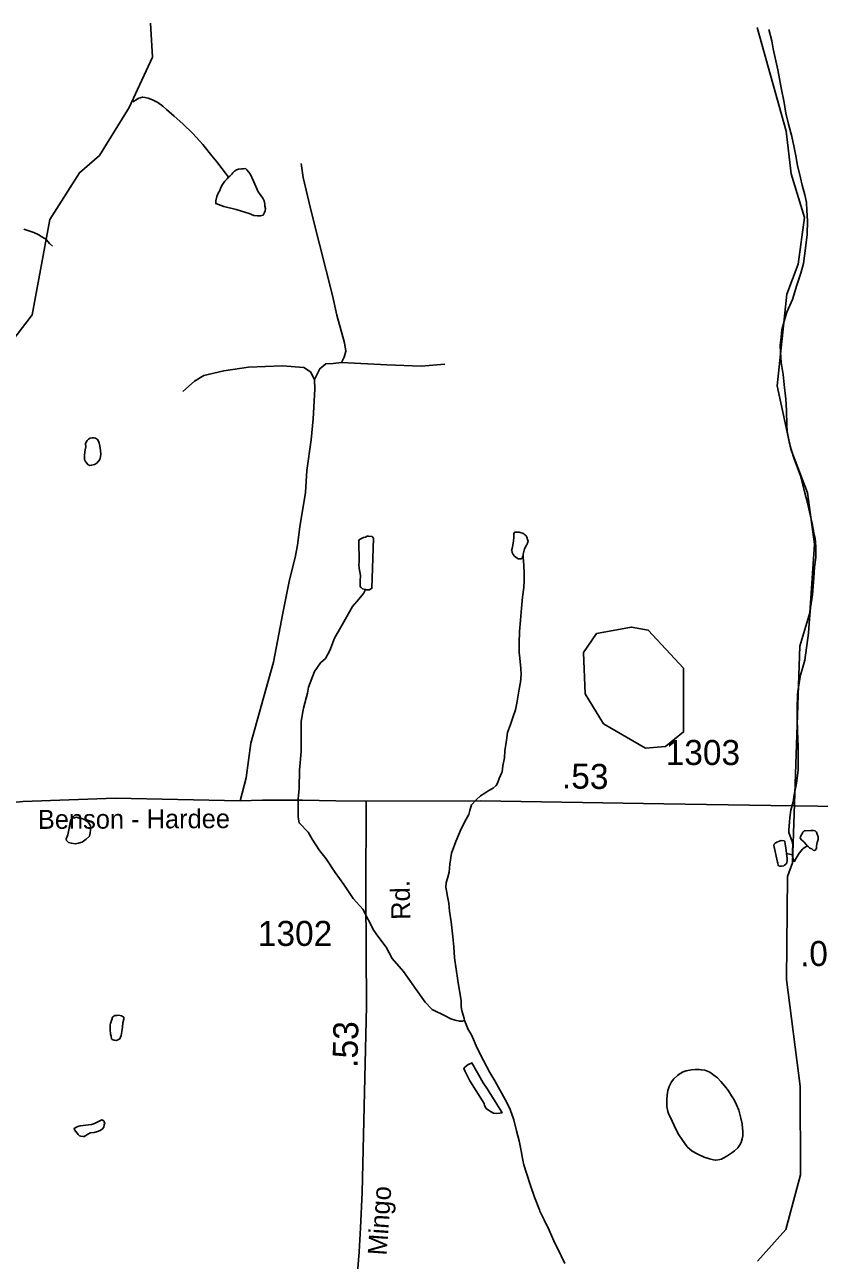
# Model space of a CAD drawing. Extents: x 2082433 to 2279600, y 546599 to 755198.
# Drawn here: x 2127316 to 2131289, y 597000 to 603173 of the extents above; entities that cross this region are included whole.
import ezdxf

# ---------------------------------------------------------------- set-up
doc = ezdxf.new("R2010")
doc.units = 0
for name, color, linetype in [('Exist Hydrographic Creek Single Shore', 7, 'Continuous'), ('Exist Hydrographic Misc Water Feature', 7, 'Continuous'), ('Exist Hydrographic Pond Under 1500 Sq Ft', 7, 'Continuous'), ('Exist Road Non-System Type 51', 7, 'Continuous'), ('Exist Road Secondary Mileage Hundredths English Label', 7, 'Continuous'), ('Exist Road Secondary Type 51 Attributed', 7, 'Continuous'), ('Exist Road Secondary Type 51 Label', 7, 'Continuous'), ('Exist Road Secondary Type 51 Number Label', 7, 'Continuous')]:
    doc.layers.add(name, color=color, linetype=linetype)

msp = doc.modelspace()

# ---------------------------------------------------------------- linework, layer by layer
at = {"layer": 'Exist Hydrographic Creek Single Shore'}
for points in [[(2127176.1, 601492.2), (2127353.7, 601723.6), (2127442.4, 602201), (2127590.5, 602434.2), (2127690.3, 602520.7), (2127839.4, 602760.5), (2127955.5, 603010.7), (2127944.6, 603180.4)], [(2130980.4, 596995.4), (2131121.5, 597153.3), (2131195.5, 597427.3), (2131193.5, 597870.3), (2131124.6, 598403.1), (2131130.5, 598918), (2131155.6, 598986.4), (2131191.4, 600068.2), (2131241.5, 600234.5), (2131264.4, 600578.5), (2131230.6, 600835.1), (2131146.5, 601053.3), (2131078.5, 601369.6), (2131126.5, 601827.9), (2131183.5, 601977.6), (2131215.7, 602209.9), (2131148.6, 602427.8), (2131122.6, 602641.5), (2130978.6, 603159.5)], [(2129019.9, 600351.6), (2129010.1, 600331.5), (2128986.1, 600303.5), (2128954.5, 600267.4), (2128896.9, 600163.1), (2128865.1, 600109), (2128841.3, 600046.9), (2128819.6, 600006.8), (2128795.4, 599984.7), (2128764.6, 599942.8), (2128735.5, 599864), (2128730.4, 599834), (2128709.8, 599758.6), (2128698.7, 599694.4), (2128697.8, 599617.3), (2128697.8, 599541.9), (2128691, 599449.4), (2128688.4, 599357.8), (2128684.1, 599306.4), (2128683.3, 599256.7), (2128683.3, 599213.9), (2128688.4, 599185.6), (2128733.4, 599138.8), (2128753.3, 599104.8), (2128789.8, 599047), (2128823.9, 599005.2), (2128868.2, 598937.3), (2128912.4, 598877.5), (2128958.6, 598807.8), (2129006.1, 598754.8), (2129061.8, 598648.6), (2129081.6, 598620.4), (2129123.7, 598564.6), (2129154.2, 598508.7), (2129210.4, 598443), (2129272.7, 598353.4), (2129318.9, 598289.5), (2129353.1, 598253.8), (2129377.1, 598241.9), (2129399, 598231.9), (2129415, 598224), (2129447.2, 598206.2), (2129469.2, 598200.2), (2129489.5, 598194.3), (2129503.4, 598194.4), (2129515.1, 598198.4)]]:
    msp.add_lwpolyline(points, dxfattribs=at)
at = {"layer": 'Exist Hydrographic Misc Water Feature'}
msp.add_line((2131155.1, 599025.4), (2131125.2, 599033.3), dxfattribs=at)
for points in [[(2131037.2, 603149.6), (2131051.3, 603093.7), (2131057.5, 603053.7), (2131081.9, 602947.9), (2131098.5, 602858), (2131112.7, 602784), (2131120.9, 602732.1), (2131135.2, 602676.2), (2131151.4, 602614.3), (2131163.7, 602560.4), (2131171.7, 602518.4), (2131179.9, 602470.5), (2131194.3, 602408.5), (2131202.5, 602372.6), (2131216.6, 602322.7), (2131224.6, 602284.7), (2131226.9, 602244.7), (2131229.1, 602192.8), (2131227.5, 602124.8), (2131219.9, 602056.7), (2131210.3, 601980.7), (2131196.5, 601932.7), (2131176.6, 601872.7), (2131154.9, 601800.5), (2131127.2, 601736.5), (2131113.5, 601692.4), (2131101.6, 601648.3), (2131097.9, 601612.4), (2131094, 601570.3), (2131094.2, 601538.3), (2131098.5, 601486.4), (2131108.8, 601426.5), (2131112.9, 601376.5), (2131121.3, 601302.6), (2131125.4, 601246.6), (2131125.8, 601172.7), (2131127.8, 601140.6), (2131131.9, 601124.6), (2131138.1, 601088.7), (2131148.1, 601050.8), (2131164.3, 600998.8), (2131194.9, 600919), (2131215.2, 600841.1), (2131229.3, 600785.2), (2131239.6, 600739.2), (2131253.9, 600681.3), (2131261.9, 600635.4), (2131268.1, 600607.4), (2131272.4, 600565.5), (2131270.8, 600511.4), (2131264.6, 600463.4), (2131260.9, 600411.5), (2131255.4, 600325.4), (2131245.7, 600259.4), (2131240, 600205.4), (2131234.3, 600133.4), (2131216.8, 599999.4), (2131207, 599963.3), (2131195.1, 599923.3), (2131181.8, 599843.3), (2131179.7, 599821.3), (2131177.9, 599761.2), (2131178.1, 599711.3), (2131180.3, 599643.3), (2131182.6, 599565.4), (2131183, 599525.4), (2131183.2, 599483.4), (2131183.2, 599449.5), (2131175.6, 599383.4), (2131163.9, 599325.4), (2131158, 599291.4), (2131146.1, 599249.3), (2131142.4, 599213.3), (2131140.3, 599189.3), (2131136.6, 599151.3), (2131136.6, 599137.3), (2131152.8, 599093.4), (2131156.9, 599075.4), (2131154.9, 599047.5), (2131155.1, 599033.4), (2131155.1, 599025.4)], [(2127857.7, 602787.8), (2127887.6, 602805.9), (2127905.4, 602812), (2127917.3, 602810), (2127933.7, 602806.1), (2127955.7, 602798.2), (2127981.7, 602784.3), (2128007.6, 602766.4), (2128025.6, 602750.5), (2128063.9, 602716.7), (2128106.2, 602678.9), (2128156.2, 602629.1), (2128206.5, 602575.3), (2128252.6, 602517.6), (2128277, 602487.6), (2128302.8, 602453.8), (2128321.1, 602431.9), (2128335.2, 602412)], [(2128335.2, 602412), (2128341.2, 602416), (2128351.2, 602426), (2128357, 602434.1), (2128365, 602442.1), (2128374.8, 602448.1), (2128384.9, 602452.1), (2128400.8, 602454.2), (2128410.9, 602454.2), (2128420.9, 602454.4), (2128426.9, 602448.4), (2128442.9, 602428.5), (2128461.1, 602388.5), (2128483.5, 602338.6), (2128493.3, 602324.7), (2128507.7, 602306.8), (2128513.6, 602292.8), (2128517.7, 602276.8), (2128517.7, 602266.8), (2128519.6, 602254.8), (2128517.9, 602242.8), (2128515.9, 602234.8), (2128507.9, 602222.7), (2128496, 602218.7), (2128480, 602218.6), (2128462, 602220.6), (2128438, 602230.4), (2128374, 602250.1), (2128311.9, 602265.9), (2128271.7, 602279.7), (2128271.7, 602293.7), (2128277.6, 602315.7), (2128283.4, 602331.8), (2128291.3, 602345.8), (2128297.3, 602359.8), (2128305.5, 602375.8), (2128317.2, 602391.9), (2128329.1, 602404), (2128335.2, 602412)], [(2127312.6, 602151.6), (2127362.7, 602135.8), (2127386.7, 602123.9), (2127398.6, 602116), (2127416.6, 602106), (2127424.8, 602098.1), (2127440.8, 602080.1), (2127454.9, 602066.2)], [(2127615.3, 601025.2), (2127619.4, 601049.2), (2127621.4, 601065.2), (2127621, 601079.3), (2127625.1, 601091.3), (2127629, 601095.3), (2127635.2, 601103.3), (2127643.2, 601107.3), (2127653, 601109.4), (2127663.1, 601109.4), (2127671.1, 601107.4), (2127681.1, 601101.5), (2127685.2, 601093.5), (2127689.1, 601083.5), (2127691.2, 601069.6), (2127695.5, 601045.5), (2127697.3, 601027.5), (2127695.5, 601015.6), (2127691.6, 601001.6), (2127677.6, 600983.5), (2127665.5, 600975.4), (2127651.6, 600973.4), (2127641.5, 600971.3), (2127633.5, 600975.3), (2127625.5, 600985.3), (2127619.6, 600991.3), (2127615.7, 601001.2), (2127615.3, 601013.2), (2127615.3, 601019.2), (2127615.3, 601025.2)], [(2129019.9, 600351.6), (2129006, 600355.5), (2128998, 600361.5), (2128993.9, 600365.5), (2128993.7, 600395.5), (2128995.7, 600421.5), (2128989.3, 600457.5), (2128987.3, 600477.4), (2128989.3, 600485.4), (2128986.9, 600599.4), (2128991, 600599.4), (2128992.8, 600603.4), (2129002.9, 600607.4), (2129010.9, 600611.5), (2129020.9, 600613.5), (2129028.9, 600617.5), (2129034.9, 600617.5), (2129052.9, 600615.7), (2129058.9, 600609.7), (2129060.9, 600605.7), (2129051.9, 600357.7), (2129039.8, 600349.7), (2129023.8, 600349.6), (2129019.9, 600351.6)], [(2129808.9, 600529), (2129808.9, 600521), (2129804.8, 600513), (2129803, 600509), (2129799.1, 600505), (2129789.3, 600504.9), (2129783.1, 600504.9), (2129779.2, 600508.9), (2129771, 600512.9), (2129764.9, 600518.8), (2129758.9, 600526.8), (2129753, 600536.8), (2129753, 600540.8), (2129750.9, 600544.8), (2129753, 600556.7), (2129754.8, 600564.7), (2129760.8, 600592.7), (2129762.6, 600612.8), (2129762.6, 600622.8), (2129762.4, 600630.8), (2129764.4, 600636.8), (2129768.3, 600638.8), (2129774.5, 600638.8), (2129782.5, 600638.9), (2129788.4, 600638.9), (2129798.5, 600634.9), (2129806.5, 600633), (2129814.5, 600627), (2129820.4, 600623), (2129822.7, 600619.1), (2129826.6, 600613.1), (2129830.7, 600601.1), (2129832.7, 600593.1), (2129830.7, 600583.1), (2129828.6, 600579.1), (2129822.7, 600569), (2129814.9, 600555.1), (2129812.8, 600549), (2129811, 600541), (2129808.9, 600529)], [(2129808.9, 600529), (2129808.9, 600521), (2129808.9, 600513.1), (2129811.2, 600471.1), (2129813.4, 600433), (2129813.4, 600397.1), (2129811.6, 600361.1), (2129805.9, 600313.1), (2129800.1, 600259.1), (2129794.4, 600199.1), (2129790.7, 600141.1), (2129788.8, 600083.1), (2129789, 600037), (2129791.1, 600009.1), (2129797.5, 599957.1), (2129797.7, 599927.1), (2129795.6, 599889.2), (2129787.8, 599853.1), (2129784.1, 599823.1), (2129776.1, 599783.1), (2129770.4, 599751), (2129758.5, 599717.1), (2129744.6, 599677), (2129730.8, 599636.9), (2129725.1, 599598.9), (2129717.5, 599544.9), (2129715.4, 599510.9), (2129707.6, 599470.9), (2129703.5, 599440.9), (2129701.7, 599436.9), (2129688, 599406.8), (2129680, 599384.8), (2129674.2, 599372.8), (2129658.2, 599358.7), (2129636.1, 599346.6), (2129616.2, 599334.5), (2129594.5, 599320.4), (2129574.4, 599302.4), (2129550.6, 599276.2), (2129542.6, 599248.3), (2129536.6, 599228.3), (2129522.9, 599204.2), (2129499.1, 599156), (2129471.4, 599092), (2129449.7, 599033.9), (2129441.9, 598979.8), (2129438.2, 598939.9), (2129432.1, 598913.9), (2129424.1, 598885.9), (2129422.4, 598863.9), (2129424.5, 598845.8), (2129430.6, 598817.9), (2129436.6, 598783.9), (2129440.9, 598743.9), (2129449.1, 598692), (2129457.5, 598616), (2129461.6, 598566.1), (2129465.9, 598512.2), (2129474.1, 598454.2), (2129482.3, 598398.2), (2129490.7, 598346.3), (2129498.9, 598298.4), (2129498.9, 598266.4), (2129501.2, 598248.4), (2129509.2, 598224.4), (2129513, 598208.4), (2129515.1, 598198.4)], [(2127531.8, 599125.4), (2127537.6, 599151.4), (2127539.6, 599169.4), (2127543.5, 599187.5), (2127545.4, 599197.5), (2127551.3, 599207.5), (2127565.3, 599211.6), (2127575.3, 599213.6), (2127589.5, 599209.7), (2127601.3, 599207.7), (2127615.3, 599201.8), (2127629.4, 599191.9), (2127635.4, 599185.9), (2127641.5, 599177.9), (2127645.6, 599169.9), (2127647.7, 599161.9), (2127643.6, 599135.9), (2127639.9, 599119.9), (2127623.9, 599103.9), (2127603.8, 599089.8), (2127585.8, 599083.7), (2127567.9, 599081.6), (2127549.9, 599083.5), (2127535.9, 599087.5), (2127525.9, 599097.4), (2127523.8, 599105.4), (2127531.8, 599125.4)], [(2131228.9, 599071.8), (2131234.9, 599065.8), (2131240.8, 599059.8), (2131250.9, 599055.8), (2131258.9, 599049.9), (2131265, 599047.9), (2131268.9, 599049.9), (2131274.9, 599057.9), (2131274.9, 599070), (2131276.9, 599080), (2131279, 599088), (2131282.6, 599102), (2131282.6, 599115.9), (2131278.8, 599129.9), (2131274.6, 599139.9), (2131268.7, 599145.9), (2131258.7, 599147.8), (2131246.8, 599147.7), (2131218.7, 599145.6), (2131212.7, 599145.6), (2131206.6, 599139.6), (2131202.7, 599131.6), (2131198.6, 599123.6), (2131194.7, 599115.6), (2131192.6, 599109.5), (2131200.6, 599101.6), (2131210.9, 599091.6), (2131223, 599077.7), (2131228.9, 599071.8)], [(2131125.2, 599033.3), (2131120.9, 599061.3), (2131119, 599079.2), (2131117, 599093.2), (2131112.9, 599095.2), (2131098.9, 599097.1), (2131085, 599093.1), (2131077, 599089.1), (2131069, 599085), (2131062.8, 599079), (2131061, 599072.9), (2131079.4, 598989.1), (2131081.5, 598985.1), (2131083.3, 598975.1), (2131085.4, 598971.1), (2131091.3, 598969.1), (2131099.3, 598969.2), (2131111.4, 598971.2), (2131115.3, 598975.2), (2131121.5, 598979.2), (2131127.4, 598985.3), (2131129.1, 598997.3), (2131129.1, 599007.3), (2131125.2, 599033.3)], [(2131228.9, 599071.8), (2131207, 599055.6), (2131189.1, 599033.6), (2131173.1, 599009.5), (2131163.1, 598991.4)], [(2131155.1, 599025.4), (2131155.1, 599017.4), (2131157.2, 599007.4), (2131161.3, 598999.4), (2131163.1, 598991.4)], [(2127745.9, 598182.7), (2127749.8, 598198.6), (2127753.9, 598206.6), (2127753.9, 598210.6), (2127755.5, 598214.6), (2127761.7, 598220.7), (2127767.6, 598222.7), (2127777.7, 598222.8), (2127787.5, 598224.8), (2127799.6, 598220.8), (2127805.6, 598218.9), (2127811.5, 598214.9), (2127811.9, 598205), (2127807.8, 598186.9), (2127805.8, 598164.9), (2127802.1, 598142.9), (2127798.2, 598122.9), (2127792, 598106.9), (2127786.1, 598102.8), (2127776.1, 598098.8), (2127764.2, 598100.8), (2127754.1, 598102.7), (2127750, 598106.7), (2127748.2, 598120.7), (2127746.1, 598130.7), (2127744.1, 598152.7), (2127743.9, 598170.7), (2127743.9, 598176.7), (2127745.9, 598182.7)], [(2129515.1, 598198.4), (2129517.4, 598194.4), (2129533.3, 598152.6), (2129549.5, 598126.6), (2129577.8, 598060.8), (2129610, 597998.9), (2129642.4, 597939.1), (2129666.6, 597897.2), (2129700.9, 597837.4), (2129729, 597785.5), (2129743.1, 597753.6), (2129761.4, 597701.7), (2129775.7, 597647.8), (2129787.8, 597597.8), (2129798.1, 597547.9), (2129806.1, 597500), (2129812.4, 597478), (2129824.3, 597436.1), (2129844.8, 597374.2), (2129865.1, 597316.2), (2129889.3, 597252.3), (2129891.4, 597246.4), (2129913.3, 597202.6), (2129937.7, 597150.6), (2129961.9, 597096.7), (2129998.4, 597022.9), (2130016.5, 596985)], [(2129613.1, 597783), (2129572.9, 597846.8), (2129542.6, 597896.7), (2129516.3, 597946.5), (2129512.4, 597958.5), (2129516.3, 597964.5), (2129524.1, 597970.5), (2129534.2, 597978.6), (2129546.1, 597982.7), (2129552.2, 597986.7), (2129608.6, 597887), (2129630.5, 597855), (2129668.9, 597793.2), (2129693.1, 597753.4), (2129703.1, 597737.4), (2129691, 597735.3), (2129673.4, 597733.3), (2129659.5, 597735.2), (2129645.1, 597743.2), (2129623.2, 597759), (2129615.2, 597773.1), (2129613.1, 597783)], [(2130760, 597502.2), (2130739.9, 597508), (2130713.8, 597515.9), (2130681.8, 597529.8), (2130653.5, 597545.7), (2130627.7, 597567.5), (2130601.7, 597605.4), (2130587.3, 597627.4), (2130575.4, 597649.3), (2130563.1, 597673.3), (2130553.1, 597695.2), (2130549.2, 597703.1), (2130537.1, 597729.1), (2130530.9, 597743), (2130526.8, 597769.1), (2130526.6, 597803.1), (2130528.7, 597825), (2130532.4, 597849), (2130538.3, 597869), (2130550.4, 597891.1), (2130562.1, 597907.2), (2130580.1, 597923.2), (2130594.1, 597933.3), (2130608.2, 597941.3), (2130623.8, 597947.4), (2130649.9, 597951.6), (2130667.9, 597953.6), (2130688, 597953.7), (2130699.9, 597951.7), (2130715.9, 597949.8), (2130742.1, 597939.9), (2130762.2, 597926), (2130780.1, 597912.1), (2130796.1, 597894.2), (2130816.4, 597870.3), (2130834.4, 597846.4), (2130850.4, 597822.4), (2130862.7, 597802.5), (2130874.6, 597776.5), (2130886.9, 597750.6), (2130896.9, 597710.7), (2130903.1, 597682.7), (2130905.1, 597660.7), (2130907.2, 597644.8), (2130907.4, 597622.8), (2130903.3, 597606.7), (2130897.6, 597588.7), (2130891.6, 597576.7), (2130881.6, 597562.7), (2130865.6, 597546.6), (2130851.6, 597536.5), (2130826, 597520.4), (2130808, 597510.3), (2130800, 597506.3), (2130792, 597504.3), (2130784, 597502.2), (2130769.8, 597500.2), (2130760, 597502.2)], [(2127636, 597676.3), (2127608.1, 597674.2), (2127594.2, 597672.1), (2127582.1, 597668.1), (2127572, 597664), (2127566.1, 597660), (2127564, 597656), (2127570.4, 597646), (2127580.4, 597634.1), (2127584.3, 597628.1), (2127590.3, 597622.1), (2127596.4, 597620.1), (2127608.3, 597618.2), (2127614.3, 597618.3), (2127622.3, 597624.3), (2127632.3, 597630.3), (2127638.3, 597634.3), (2127644.4, 597636.4), (2127664.3, 597638.4), (2127680.3, 597644.5), (2127694.4, 597648.6), (2127706.1, 597656.6), (2127712.1, 597664.6), (2127714.1, 597676.6), (2127716.2, 597684.6), (2127714.1, 597690.6), (2127714.1, 597694.6), (2127708.2, 597698.6), (2127702, 597702.6), (2127682.1, 597692.5), (2127666.1, 597684.5), (2127650.1, 597678.4), (2127636, 597676.3)]]:
    msp.add_lwpolyline(points, dxfattribs=at)
at = {"layer": 'Exist Hydrographic Pond Under 1500 Sq Ft'}
msp.add_lwpolyline([(2130419.4, 599559), (2130519.5, 599566.8), (2130610.5, 599640.4), (2130609.5, 599958.7), (2130433.6, 600149.2), (2130350.5, 600164), (2130175.4, 600131.5), (2130109.6, 600037.7), (2130118.4, 599830.8), (2130210.5, 599681.3), (2130419.4, 599559)], dxfattribs=at)
at = {"layer": 'Exist Road Non-System Type 51'}
for points in [[(2128899.8, 601485.1), (2128913, 601511.7), (2128921.3, 601543.2), (2128914.7, 601584.7), (2128876.5, 601722.4), (2128854.9, 601820.3), (2128789.4, 602076.7), (2128745.4, 602255.1), (2128708.9, 602409.4), (2128698.1, 602479.9)], [(2128764.5, 601401.3), (2128744.6, 601439.5), (2128711.4, 601461.1), (2128605.2, 601469.4), (2128435.9, 601462.7), (2128311.5, 601444.5), (2128211.9, 601421.2), (2128165.5, 601393), (2128107.4, 601341.6)], [(2128764.5, 601401.3), (2128792.7, 601454.4), (2128822.6, 601479.3), (2128859.1, 601481), (2128899.8, 601485.1)], [(2128899.8, 601485.1), (2129127.1, 601473.5), (2129298, 601466.9), (2129417.5, 601476.8)], [(2128392.9, 599296.1), (2128423.7, 599410.9), (2128447.4, 599583.4), (2128511, 599810.3), (2128559.6, 599988.3), (2128606.9, 600233.1), (2128640.1, 600400.7), (2128669.1, 600511), (2128680.7, 600572.4), (2128692.3, 600665.4), (2128719.7, 600835.5), (2128726.3, 600946.6), (2128748.7, 601100.1), (2128757.9, 601203.8), (2128766.2, 601353.2), (2128764.5, 601401.3)]]:
    msp.add_lwpolyline(points, dxfattribs=at)
at = {"layer": 'Exist Road Secondary Type 51 Attributed'}
for points in [[(2129023.3, 599294.4), (2128872.7, 599296.5), (2128704.8, 599298.9), (2128504.8, 599299.2), (2128392.9, 599296.1), (2127769.7, 599309.6), (2127307.8, 599292.7), (2127170.7, 599279), (2126995.7, 599264.6), (2126913.3, 599263.2), (2126848, 599267.5), (2126758.4, 599279.7)], [(2128950.1, 596466.1), (2128954.5, 596520.1), (2128971, 596812.4), (2128988.2, 597041.9), (2128995, 597162.7), (2129003.6, 597338.3), (2129025, 598270.1), (2129022.4, 598828.5), (2129023.3, 599294.4)], [(2131894, 599263), (2131784.2, 599259.9), (2131632.8, 599264.8), (2131046.2, 599272.3), (2130511.9, 599280.6), (2129595.9, 599295.5), (2129023.3, 599294.4)]]:
    msp.add_lwpolyline(points, dxfattribs=at)

# ---------------------------------------------------------------- texts
at = {"layer": 'Exist Road Secondary Mileage Hundredths English Label'}
for s, rotation, p in [('.53', 359.17962, (2130001.8, 599357.9)), ('.02', 1.27316, (2131193.9, 598468.5)), ('.53', 88.76841, (2128980, 597961.2))]:
    msp.add_text(s, height=125, rotation=rotation, dxfattribs=at).set_placement(p)
at = {"layer": 'Exist Road Secondary Type 51 Label'}
for s, rotation, p in [('Benson - Hardee', 0.23905, (2127382.5, 599155.6)), ('Rd.', 91.2927, (2129245.1, 598702.4)), ('Mingo', 86.00432, (2129125.6, 597022.4))]:
    msp.add_text(s, height=95, rotation=rotation, dxfattribs=at).set_placement(p)
at = {"layer": 'Exist Road Secondary Type 51 Number Label'}
for s, p in [('1303', (2130521, 599474.8)), ('1302', (2128482.1, 598570.9))]:
    msp.add_text(s, height=125, dxfattribs=at).set_placement(p)

doc.saveas('drawing.dxf')
